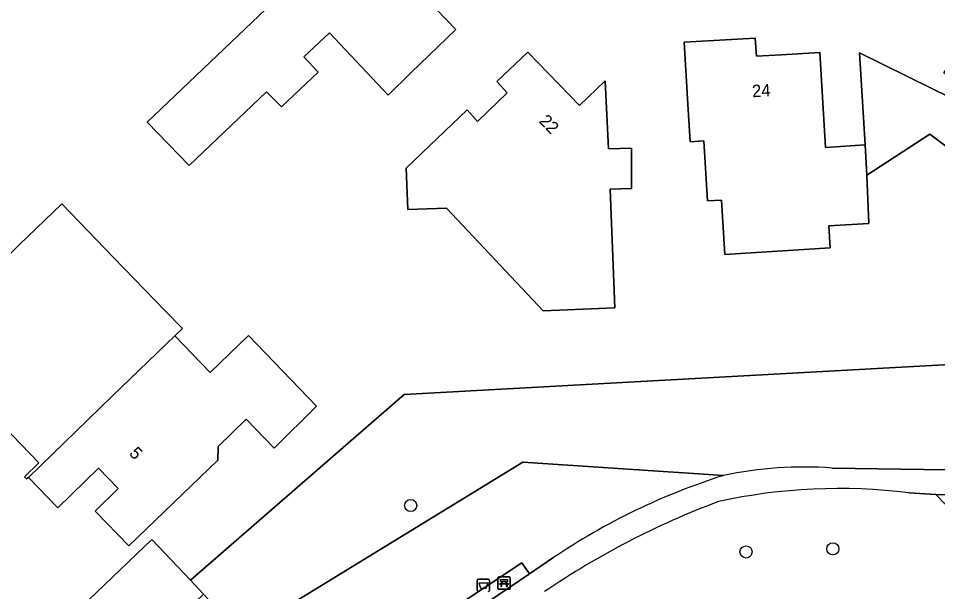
# Model space of a CAD drawing. Extents: x 159499 to 160349, y 382524 to 383273.
# Drawn here: x 159921.7 to 159995.6, y 382906.1 to 382952.3 of the extents above; entities that cross this region are included whole.
import ezdxf

# ---------------------------------------------------------------- set-up
doc = ezdxf.new("R2010")
doc.units = 0
for name, color, linetype in [('IMGEO_Afvalbak', 7, 'Continuous'), ('IMGEO_Bank', 7, 'Continuous'), ('IMGEO_Boom', 7, 'Continuous'), ('IMGEO_Erf', 7, 'Continuous'), ('IMGEO_Groenvoorziening', 7, 'Continuous'), ('IMGEO_Pand', 7, 'Continuous'), ('IMGEO_Pand_nummerreeks', 7, 'Continuous'), ('IMGEO_Rijbaan_lokaal_open', 7, 'Continuous'), ('IMGEO_Voetpad_halfverhard', 7, 'Continuous'), ('IMGEO_Voetpad_open', 7, 'Continuous')]:
    doc.layers.add(name, color=color, linetype=linetype)

msp = doc.modelspace()

# ---------------------------------------------------------------- linework, layer by layer
at = {"layer": 'IMGEO_Afvalbak'}
for p, q in [((159958.562, 382906.212), (159958.562, 382907.012)), ((159958.562, 382907.012), (159958.562, 382906.212)), ((159958.662, 382907.112), (159959.452, 382907.112)), ((159959.452, 382907.112), (159958.662, 382907.112)), ((159959.552, 382907.012), (159959.552, 382906.212)), ((159959.552, 382906.212), (159959.552, 382907.012))]:
    msp.add_line(p, q, dxfattribs=at)
msp.add_lwpolyline([(159958.705, 382906.826), (159959.409, 382906.826), (159959.26, 382906.356), (159958.854, 382906.356), (159958.705, 382906.826)], dxfattribs=at)
for centre, start, end in [((159958.662, 382907.012), 90, 180), ((159958.662, 382907.012), 90, 180), ((159959.452, 382907.012), 0, 90), ((159959.452, 382907.012), 360, 90), ((159958.662, 382906.212), 180, 270), ((159958.662, 382906.212), 180, 270), ((159959.452, 382906.212), 270, 0), ((159959.452, 382906.212), 270, 0)]:
    msp.add_arc(centre, 0.1, start, end, dxfattribs=at)
at = {"layer": 'IMGEO_Bank'}
for p, q in [((159960.22, 382906.378), (159960.22, 382907.219)), ((159960.22, 382907.219), (159960.22, 382906.378)), ((159960.295, 382907.303), (159961.136, 382907.303)), ((159961.136, 382907.303), (159960.295, 382907.303)), ((159960.861, 382906.921), (159960.579, 382906.921)), ((159961.22, 382907.228), (159961.22, 382906.387)), ((159961.22, 382906.387), (159961.22, 382907.228)), ((159961.145, 382906.303), (159960.304, 382906.303)), ((159960.304, 382906.303), (159961.145, 382906.303)), ((159960.917, 382906.701), (159960.524, 382906.701)), ((159960.529, 382906.809), (159960.529, 382906.915)), ((159960.573, 382906.915), (159960.573, 382906.809)), ((159960.579, 382906.803), (159960.861, 382906.803)), ((159960.867, 382906.809), (159960.867, 382906.915)), ((159960.911, 382906.915), (159960.911, 382906.809))]:
    msp.add_line(p, q, dxfattribs=at)
for points in [[(159960.523, 382906.921), (159960.437, 382906.921), (159960.437, 382907.082), (159961, 382907.082), (159961, 382906.921), (159960.917, 382906.921)], [(159960.467, 382906.701), (159960.325, 382906.701), (159960.437, 382906.803), (159960.523, 382906.803)], [(159960.517, 382906.694), (159960.517, 382906.487), (159960.474, 382906.487), (159960.474, 382906.694)], [(159960.917, 382906.803), (159961, 382906.803), (159961.112, 382906.701), (159960.973, 382906.701)], [(159960.967, 382906.694), (159960.967, 382906.487), (159960.923, 382906.487), (159960.923, 382906.694)]]:
    msp.add_lwpolyline(points, dxfattribs=at)
for centre, radius, start, end in [((159960.298, 382907.225), 0.0779, 92.4484, 184.28452), ((159960.298, 382907.225), 0.0779, 92.4484, 184.28452), ((159960.522, 382906.914), 0.00671, 2.89567, 87.10433), ((159960.579, 382906.914), 0.00671, 92.89567, 177.10433), ((159960.861, 382906.914), 0.00671, 2.89567, 87.10433), ((159960.918, 382906.914), 0.00671, 92.89567, 177.10433), ((159961.142, 382907.225), 0.0779, 2.4484, 94.28452), ((159961.142, 382907.225), 0.0779, 2.4484, 94.28452), ((159960.298, 382906.381), 0.0779, 182.4484, 274.28452), ((159960.298, 382906.381), 0.0779, 182.4484, 274.28452), ((159960.467, 382906.694), 0.00671, 2.89567, 87.10433), ((159960.524, 382906.694), 0.00671, 92.89567, 177.10433), ((159960.522, 382906.81), 0.00671, 272.89567, 357.10433), ((159960.579, 382906.81), 0.00671, 182.89567, 267.10433), ((159960.861, 382906.81), 0.00671, 272.89567, 357.10433), ((159960.918, 382906.81), 0.00671, 182.89567, 267.10433), ((159960.916, 382906.694), 0.00671, 2.89567, 87.10433), ((159960.973, 382906.694), 0.00671, 92.89567, 177.10433), ((159961.142, 382906.381), 0.0779, 272.4484, 4.28452), ((159961.142, 382906.381), 0.0779, 272.4484, 4.28452)]:
    msp.add_arc(centre, radius, start, end, dxfattribs=at)
at = {"layer": 'IMGEO_Boom'}
for centre in [(159953.21, 382913.043), (159987.158, 382909.558), (159980.182, 382909.307)]:
    msp.add_circle(centre, 0.489, dxfattribs=at)
at = {"layer": 'IMGEO_Erf'}
for points in [[(159942.81, 382945.14), (159941.604, 382946.347), (159935.384, 382940.398), (159932.01, 382943.902), (159946.063, 382957.311), (159949.681, 382960.761), (159952.057, 382958.267), (159951.15, 382957.329), (159951.983, 382956.452), (159951.534, 382956.005), (159952.617, 382954.913), (159953.046, 382955.323), (159956.844, 382951.362), (159953.255, 382947.882), (159951.397, 382946.081), (159946.683, 382951.101), (159944.62, 382949.165), (159945.781, 382947.93)], [(159954.14, 382941.432), (159957.752, 382944.888), (159958.595, 382943.951), (159960.982, 382946.257), (159960.129, 382947.168), (159962.629, 382949.538), (159966.781, 382945.233), (159968.86, 382947.238), (159969.117, 382941.759), (159970.967, 382941.803), (159970.967, 382938.572), (159969.253, 382938.503), (159969.636, 382928.964), (159963.862, 382928.723), (159956.079, 382936.968), (159952.979, 382936.874), (159952.838, 382940.186)]]:
    msp.add_lwpolyline(points, close=True, dxfattribs=at)
for points in [[(159975.215, 382950.328), (159980.908, 382950.668), (159981.031, 382949.203), (159983.01, 382949.322), (159986.119, 382949.51), (159986.572, 382941.868), (159989.763, 382942.076), (159989.318, 382949.49), (159995.132, 382946.61), (159996.488, 382945.938), (159997.261, 382946.967), (159996.091, 382947.877), (159998.929, 382951.684), (160000, 382950.12)], [(160000, 382939.157), (159994.951, 382942.922), (159989.908, 382939.638), (159990.066, 382935.741), (159986.85, 382935.55), (159986.956, 382933.774), (159978.486, 382933.238), (159978.209, 382937.627), (159977.093, 382937.562), (159976.788, 382942.385), (159975.68, 382942.311), (159975.504, 382945.337), (159975.215, 382950.328)], [(159921.516, 382933.806), (159921.728, 382934.012), (159925.152, 382937.333), (159929.319, 382933.012), (159933.461, 382928.717), (159934.846, 382927.28), (159934.237, 382926.693), (159937.078, 382923.748), (159940.168, 382926.726), (159945.647, 382921.045), (159942.223, 382917.661), (159939.983, 382919.987), (159937.724, 382917.781), (159937.687, 382916.689), (159930.545, 382909.796), (159927.827, 382912.599), (159929.691, 382914.412), (159928.102, 382916.047), (159924.833, 382912.869), (159922.464, 382915.308), (159922.3, 382915.182), (159922.161, 382915.344), (159923.31, 382916.485), (159920.455, 382919.422)], [(159927.32, 382905.439), (159932.4, 382910.308), (159935.493, 382907.023), (159952.688, 382921.969), (160000, 382924.568)]]:
    msp.add_lwpolyline(points, dxfattribs=at)
at = {"layer": 'IMGEO_Groenvoorziening'}
for points in [[(160017.276, 382919.096), (160020.444, 382934.49), (160020.156, 382934.712), (160017.142, 382937.168), (160015.807, 382935.383), (160015.93, 382935.29), (160015.81, 382935.13), (160015.706, 382935.209), (160009.503, 382926.949), (160007.956, 382925.066), (160000, 382924.568), (159952.688, 382921.969), (159935.493, 382907.023), (159936.535, 382905.918), (159939.597, 382902.666), (159962.238, 382916.541), (159978.374, 382915.464)], [(160000, 382913.869), (159995.441, 382913.932), (159998.661, 382910.612), (160007.888, 382911.617), (160013.958, 382912.93), (160018.766, 382914.115), (160023.698, 382915.886), (160026.463, 382917.219), (160023.853, 382919.231)], [(159978.374, 382915.464), (159962.238, 382916.541), (159939.597, 382902.666), (159932.489, 382895.814), (159928.789, 382892.248), (159930.59, 382890.343)], [(159987.109, 382916.059), (160000, 382915.872)], [(160004.058, 382905.797), (159999.841, 382909.394), (159998.661, 382910.612), (159995.441, 382913.932), (159993.278, 382914.055)], [(159956.171, 382904.463), (159962.152, 382908.427), (159962.759, 382907.542), (159964.645, 382908.821)]]:
    msp.add_lwpolyline(points, dxfattribs=at)
for centre, radius, start, end in [((159984.823, 382885.202), 30.941, 85.76316, 102.03041), ((159994.496, 382864.636), 53.323, 107.59863, 124.04292), ((159987.63, 382869.501), 44.911, 82.7755, 102.44082), ((160001.146, 382851.541), 66.023, 110.56391, 124.25603)]:
    msp.add_arc(centre, radius, start, end, dxfattribs=at)
at = {"layer": 'IMGEO_Pand'}
for points in [[(159953.255, 382947.882), (159956.844, 382951.362), (159953.046, 382955.323), (159952.617, 382954.913), (159951.534, 382956.005), (159951.983, 382956.452), (159951.15, 382957.329), (159952.057, 382958.267), (159949.681, 382960.761), (159946.063, 382957.311), (159932.01, 382943.902), (159935.384, 382940.398), (159941.604, 382946.347), (159942.81, 382945.14), (159945.781, 382947.93), (159944.62, 382949.165), (159946.683, 382951.101), (159951.397, 382946.081)], [(159986.119, 382949.51), (159983.01, 382949.322), (159981.031, 382949.203), (159980.908, 382950.668), (159975.215, 382950.328), (159975.504, 382945.337), (159975.68, 382942.311), (159976.788, 382942.385), (159977.093, 382937.562), (159978.209, 382937.627), (159978.486, 382933.238), (159986.956, 382933.774), (159986.85, 382935.55), (159990.066, 382935.741), (159989.908, 382939.638), (159989.763, 382942.076), (159986.572, 382941.868)], [(159952.979, 382936.874), (159956.079, 382936.968), (159963.862, 382928.723), (159969.636, 382928.964), (159969.253, 382938.503), (159970.967, 382938.572), (159970.967, 382941.803), (159969.117, 382941.759), (159968.86, 382947.238), (159966.781, 382945.233), (159962.629, 382949.538), (159960.129, 382947.168), (159960.982, 382946.257), (159958.595, 382943.951), (159957.752, 382944.888), (159954.14, 382941.432), (159952.838, 382940.186)], [(159934.237, 382926.693), (159934.846, 382927.28), (159933.461, 382928.717), (159929.319, 382933.012), (159925.152, 382937.333), (159921.728, 382934.012), (159921.516, 382933.806), (159917.927, 382930.324), (159918.595, 382929.636), (159916.539, 382927.685), (159916.063, 382928.223), (159913.832, 382926.031), (159916.046, 382923.73), (159912.095, 382919.928), (159916.926, 382914.889), (159919.862, 382917.718), (159919.343, 382918.273), (159920.455, 382919.422), (159923.31, 382916.485), (159922.161, 382915.344), (159922.3, 382915.182), (159922.464, 382915.308), (159929.208, 382921.845)], [(159929.208, 382921.845), (159922.464, 382915.308), (159924.833, 382912.869), (159928.102, 382916.047), (159929.691, 382914.412), (159927.827, 382912.599), (159930.545, 382909.796), (159937.687, 382916.689), (159937.724, 382917.781), (159939.983, 382919.987), (159942.223, 382917.661), (159945.647, 382921.045), (159940.168, 382926.726), (159937.078, 382923.748), (159934.237, 382926.693)]]:
    msp.add_lwpolyline(points, close=True, dxfattribs=at)
msp.add_lwpolyline([(159996.488, 382945.938), (159995.132, 382946.61), (159989.318, 382949.49), (159989.763, 382942.076), (159989.908, 382939.638), (159994.951, 382942.922), (160000, 382939.157)], dxfattribs=at)
at = {"layer": 'IMGEO_Rijbaan_lokaal_open'}
msp.add_lwpolyline([(159879.911, 382951.31), (159884.682, 382964.447), (159880.433, 382965.991), (159876.322, 382954.768), (159874.404, 382949.452), (159879.627, 382940.809), (159879.787, 382940.656), (159881.307, 382939.023), (159908.873, 382910.281), (159927.427, 382890.935), (159928.789, 382892.248), (159932.489, 382895.814), (159929.428, 382899.056), (159936.535, 382905.918), (159935.493, 382907.023), (159932.4, 382910.308), (159927.32, 382905.439)], dxfattribs=at)
at = {"layer": 'IMGEO_Voetpad_halfverhard'}
for points in [[(160000, 382915.872), (159987.109, 382916.059)], [(159993.278, 382914.055), (159995.441, 382913.932), (160000, 382913.869)], [(159964.645, 382908.821), (159962.759, 382907.542), (159956.778, 382903.484), (159937.517, 382890.414)]]:
    msp.add_lwpolyline(points, dxfattribs=at)
for centre, radius, start, end in [((159984.823, 382885.202), 30.941, 85.76316, 102.03041), ((159994.496, 382864.636), 53.323, 107.59863, 124.04292), ((159987.63, 382869.501), 44.911, 82.7755, 102.44082), ((160001.146, 382851.541), 66.023, 110.56391, 124.25603)]:
    msp.add_arc(centre, radius, start, end, dxfattribs=at)
at = {"layer": 'IMGEO_Voetpad_open'}
msp.add_lwpolyline([(159962.759, 382907.542), (159962.152, 382908.427), (159956.171, 382904.463), (159956.778, 382903.484)], close=True, dxfattribs=at)

# ---------------------------------------------------------------- texts
at = {"layer": 'IMGEO_Pand_nummerreeks'}
for s, rotation, p in [('24', 3.44348, (159980.694, 382945.897)), ('22', 313.96354, (159963.476, 382943.935)), ('5', 314.18256, (159930.511, 382917.184))]:
    msp.add_text(s, height=1, rotation=rotation, dxfattribs=at).set_placement(p)

doc.saveas('drawing.dxf')
